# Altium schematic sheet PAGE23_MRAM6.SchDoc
size 381 x 381 mm; SheetNumber: 24; SheetTotal: 28
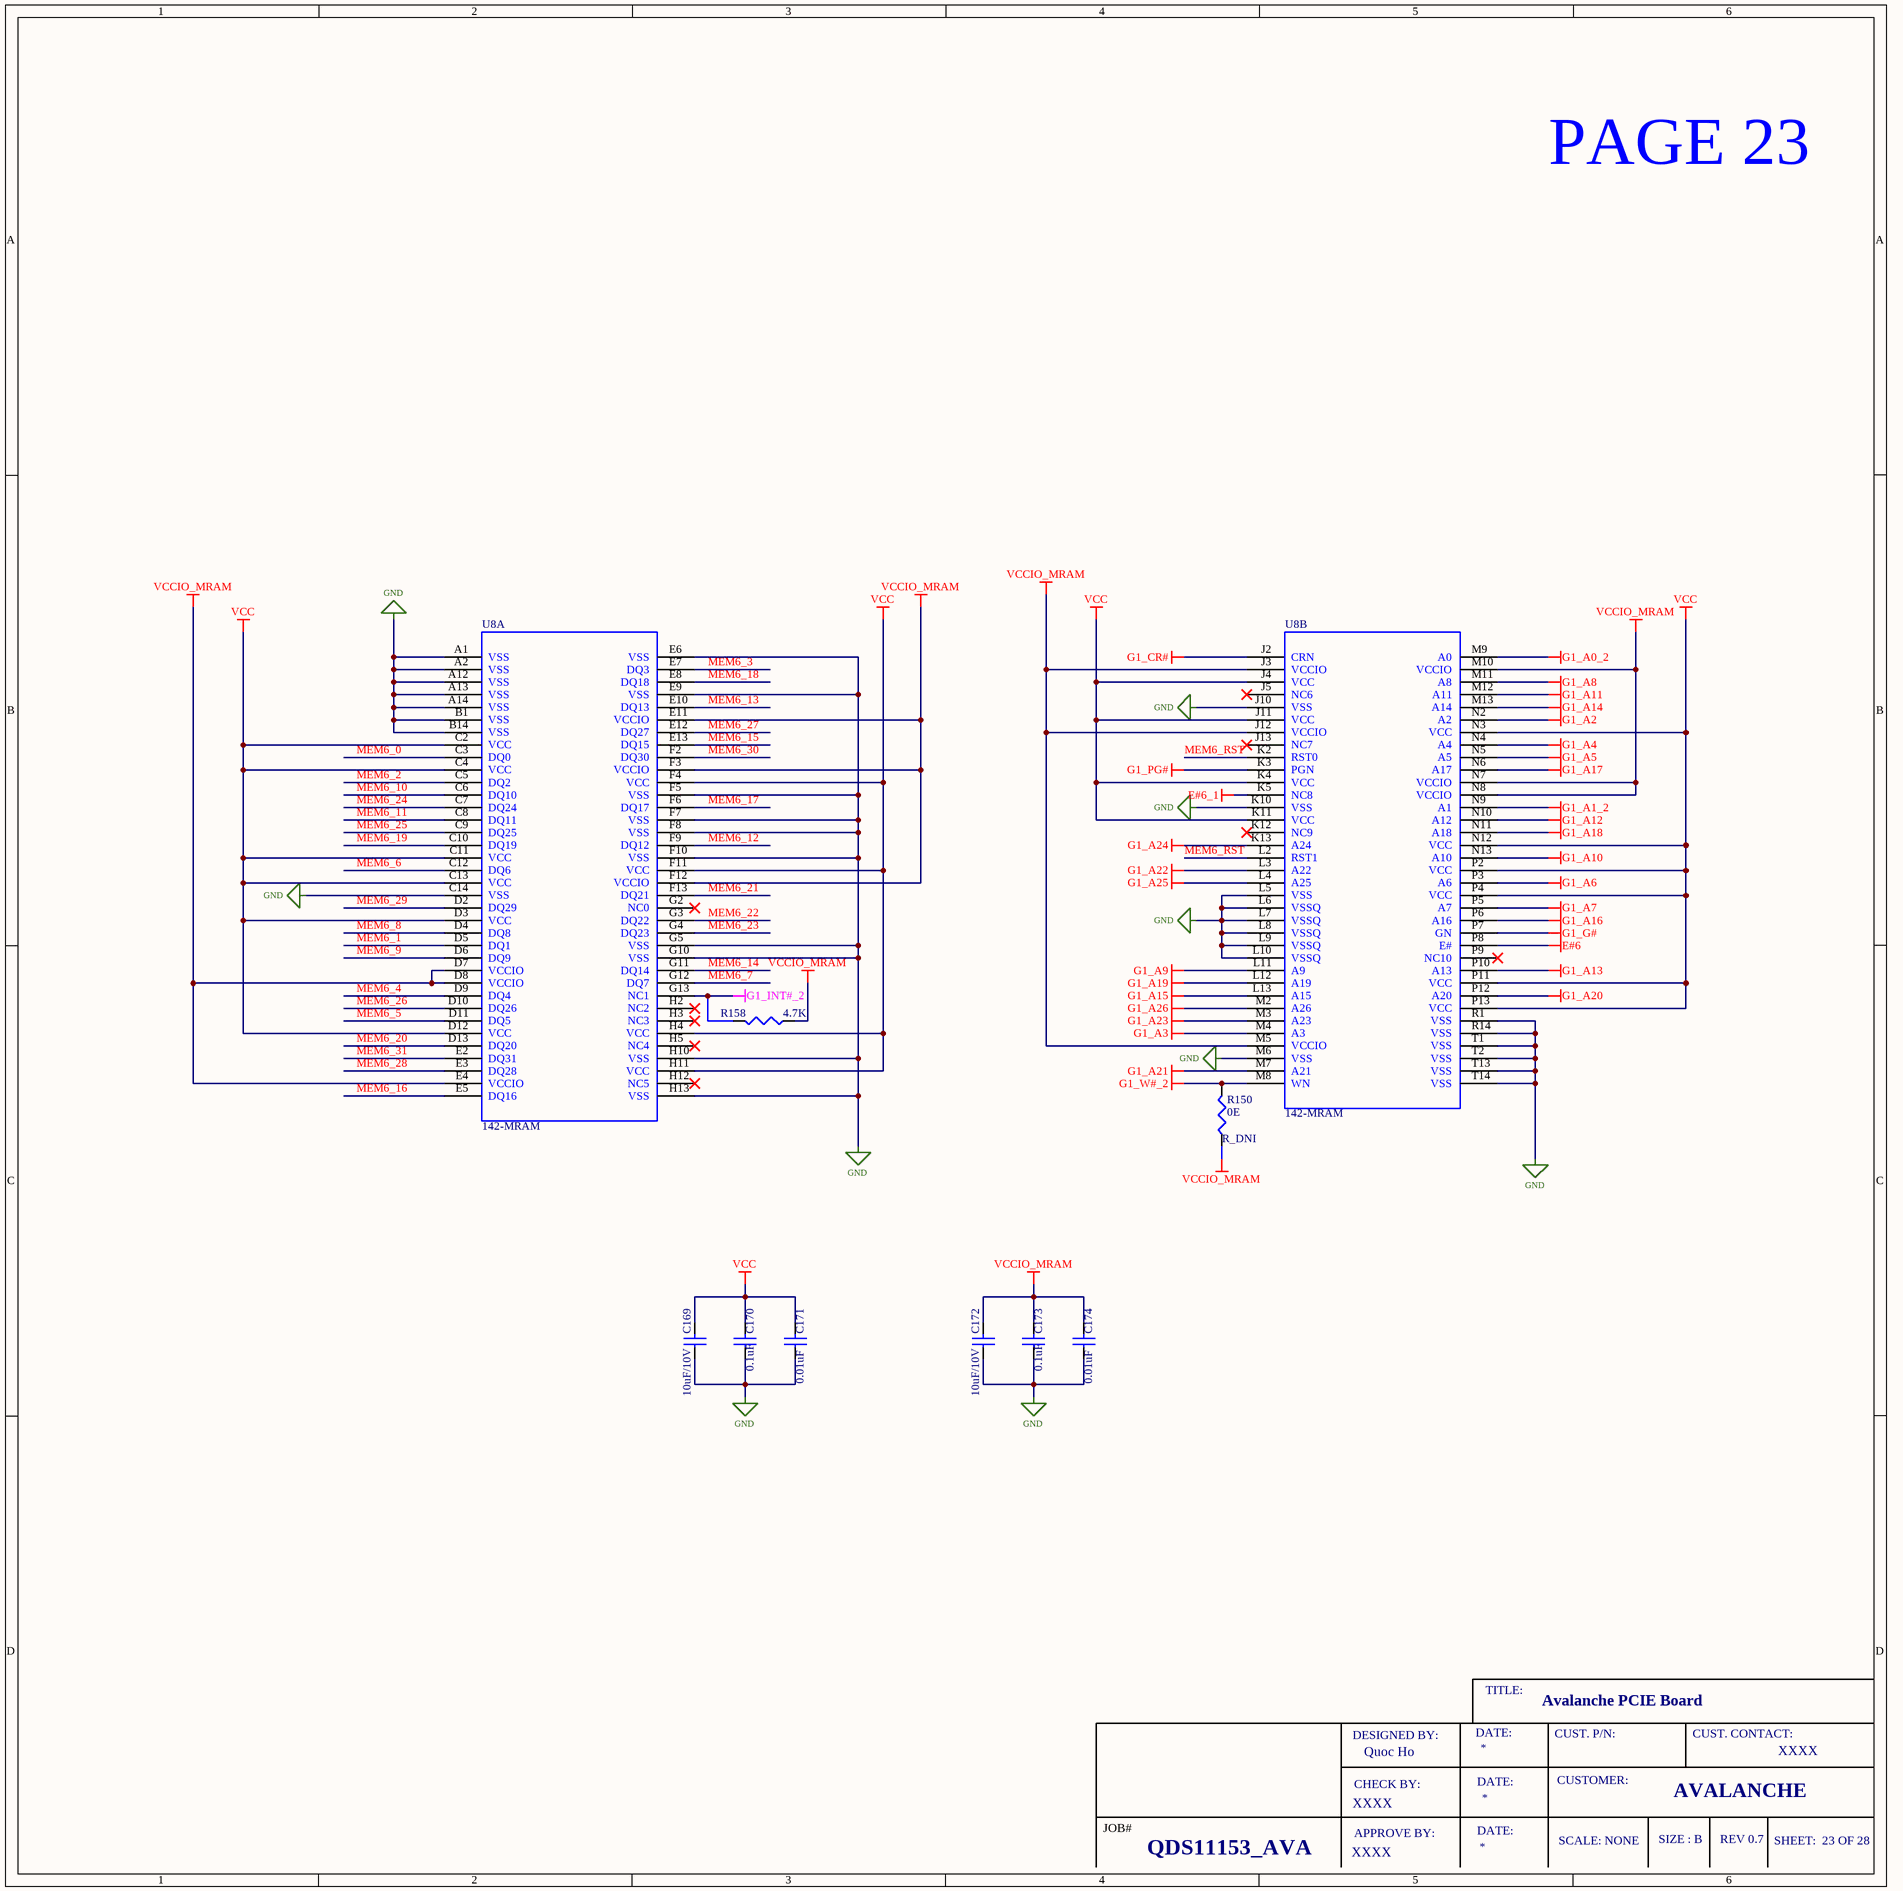
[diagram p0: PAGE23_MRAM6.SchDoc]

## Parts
C169  10uF/10V  [CN_0402]
C170  0.1uF  [CN_0402]
C171  0.01uF  [CN_0402]
C172  10uF/10V  [CN_0402]
C173  0.1uF  [CN_0402]
C174  0.01uF  [CN_0402]
R150  0E  [RN_0402]
R158  4.7K  [RN_0402]
U8  142-MRAM  [142-MRAM]  (parts A,B of 2)

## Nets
E#6: U8.P8(E#)
E#6_1: U8.K5(NC8)
G1_A0_2: U8.M9(A0)
G1_A1_2: U8.N9(A1)
G1_A2: U8.N2(A2)
G1_A3: U8.M4(A3)
G1_A4: U8.N4(A4)
G1_A5: U8.N5(A5)
G1_A6: U8.P3(A6)
G1_A7: U8.P5(A7)
G1_A8: U8.M11(A8)
G1_A9: U8.L11(A9)
G1_A10: U8.N13(A10)
G1_A11: U8.M12(A11)
G1_A12: U8.N10(A12)
G1_A13: U8.P10(A13)
G1_A14: U8.M13(A14)
G1_A15: U8.L13(A15)
G1_A16: U8.P6(A16)
G1_A17: U8.N6(A17)
G1_A18: U8.N11(A18)
G1_A19: U8.L12(A19)
G1_A20: U8.P12(A20)
G1_A21: U8.M7(A21)
G1_A22: U8.L3(A22)
G1_A23: U8.M3(A23)
G1_A24: U8.K13(A24)
G1_A25: U8.L4(A25)
G1_A26: U8.M2(A26)
G1_CR#: U8.J2(CRN)
G1_G#: U8.P7(GN)
G1_INT#_2: R158.2 U8.G13(NC1)
G1_PG#: U8.K3(PGN)
G1_W#_2: R150.2 U8.M8(WN)
GND: C169.1 C170.1 C171.1 C172.1 C173.1 C174.1 U8.A1(VSS) U8.A2(VSS) U8.A12(VSS) U8.A13(VSS) U8.A14(VSS) U8.B1(VSS) U8.B14(VSS) U8.C14(VSS) U8.E6(VSS) U8.E9(VSS) U8.F5(VSS) U8.F7(VSS) U8.F8(VSS) U8.F10(VSS) U8.G5(VSS) U8.G10(VSS) U8.H10(VSS) U8.H13(VSS) U8.J10(VSS) U8.K10(VSS) U8.L5(VSS) U8.L6(VSSQ) U8.L7(VSSQ) U8.L8(VSSQ) U8.L9(VSSQ) U8.L10(VSSQ) U8.M6(VSS) U8.R1(VSS) U8.R14(VSS) U8.T1(VSS) U8.T2(VSS) U8.T13(VSS) U8.T14(VSS)
VCC: C169.2 C170.2 C171.2 U8.C2(VCC) U8.C4(VCC) U8.C11(VCC) U8.C13(VCC) U8.D3(VCC) U8.D12(VCC) U8.F4(VCC) U8.F11(VCC) U8.H4(VCC) U8.H11(VCC) U8.J4(VCC) U8.J11(VCC) U8.K4(VCC) U8.K11(VCC) U8.N3(VCC) U8.N12(VCC) U8.P2(VCC) U8.P4(VCC) U8.P11(VCC) U8.P13(VCC)
VCCIO_MRAM: C172.2 C173.2 C174.2 R150.1 R158.1 U8.D7(VCCIO) U8.D8(VCCIO) U8.E4(VCCIO) U8.E11(VCCIO) U8.F3(VCCIO) U8.F12(VCCIO) U8.J3(VCCIO) U8.J12(VCCIO) U8.M5(VCCIO) U8.M10(VCCIO) U8.N7(VCCIO) U8.N8(VCCIO)
MEM6_0: U8.C3(DQ0)
MEM6_1: U8.D5(DQ1)
MEM6_2: U8.C5(DQ2)
MEM6_3: U8.E7(DQ3)
MEM6_4: U8.D9(DQ4)
MEM6_5: U8.D11(DQ5)
MEM6_6: U8.C12(DQ6)
MEM6_7: U8.G12(DQ7)
MEM6_8: U8.D4(DQ8)
MEM6_9: U8.D6(DQ9)
MEM6_10: U8.C6(DQ10)
MEM6_11: U8.C8(DQ11)
MEM6_12: U8.F9(DQ12)
MEM6_13: U8.E10(DQ13)
MEM6_14: U8.G11(DQ14)
MEM6_15: U8.E13(DQ15)
MEM6_16: U8.E5(DQ16)
MEM6_17: U8.F6(DQ17)
MEM6_18: U8.E8(DQ18)
MEM6_19: U8.C10(DQ19)
MEM6_20: U8.D13(DQ20)
MEM6_21: U8.F13(DQ21)
MEM6_22: U8.G3(DQ22)
MEM6_23: U8.G4(DQ23)
MEM6_24: U8.C7(DQ24)
MEM6_25: U8.C9(DQ25)
MEM6_26: U8.D10(DQ26)
MEM6_27: U8.E12(DQ27)
MEM6_28: U8.E3(DQ28)
MEM6_29: U8.D2(DQ29)
MEM6_30: U8.F2(DQ30)
MEM6_31: U8.E2(DQ31)
MEM6_RST: U8.K2(RST0) U8.L2(RST1)

Not connected (* = marked no-connect by the designer): U8 G2(NC0)* H2(NC2)* H3(NC3)* H5(NC4)* H12(NC5)* J5(NC6)* J13(NC7)* K12(NC9)* P9(NC10)*

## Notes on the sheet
- PAGE 23
- TITLE:
- Avalanche PCIE Board
- DESIGNED BY:
- CHECK BY:
- Quoc Ho
- DATE:
- CUST. P/N:
- CUSTOMER:
- CUST. CONTACT:
- XXXX
- JOB#
- APPROVE BY:
- SCALE: NONE
- SIZE : B
- AVALANCHE
- REV 0.7
- SHEET:  23 OF 28
- QDS11153_AVA

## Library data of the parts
C169 C172 = CAP: CAP CER 10UF 10V X5R 0402; Manufacturer Part Number: GRM155R61A106ME11D; Manufacturer: Murata Electronics
C170 C173 = CAP: CAP CER 0.1UF 50V X7R 0402; Manufacturer: Murata Electronics; Manufacturer Part Number: GCM155R71H104KE02J
C171 C174 = CAP: 0.01 µF, 25 V, 0402 [1005 Metric], ± 10%, X7R; Manufacturer Part Number: CC0402JRX7R8BB103; Manufacturer: YAGEO
R150 = RES: RES 0 OHM JUMPER 1/16W 0402; Manufacturer Part Number: RC0402FR-070RL_DNI; Manufacturer: YAGEO
R158 = RES: RES 4.7K OHM 1% 1/16W 0402; Manufacturer: YAGEO; Manufacturer Part Number: RC0402FR-134K7L
U8 = 142-MRAM: IC 142-MRAM MEMORY; Manufacturer: Avalanche Technology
